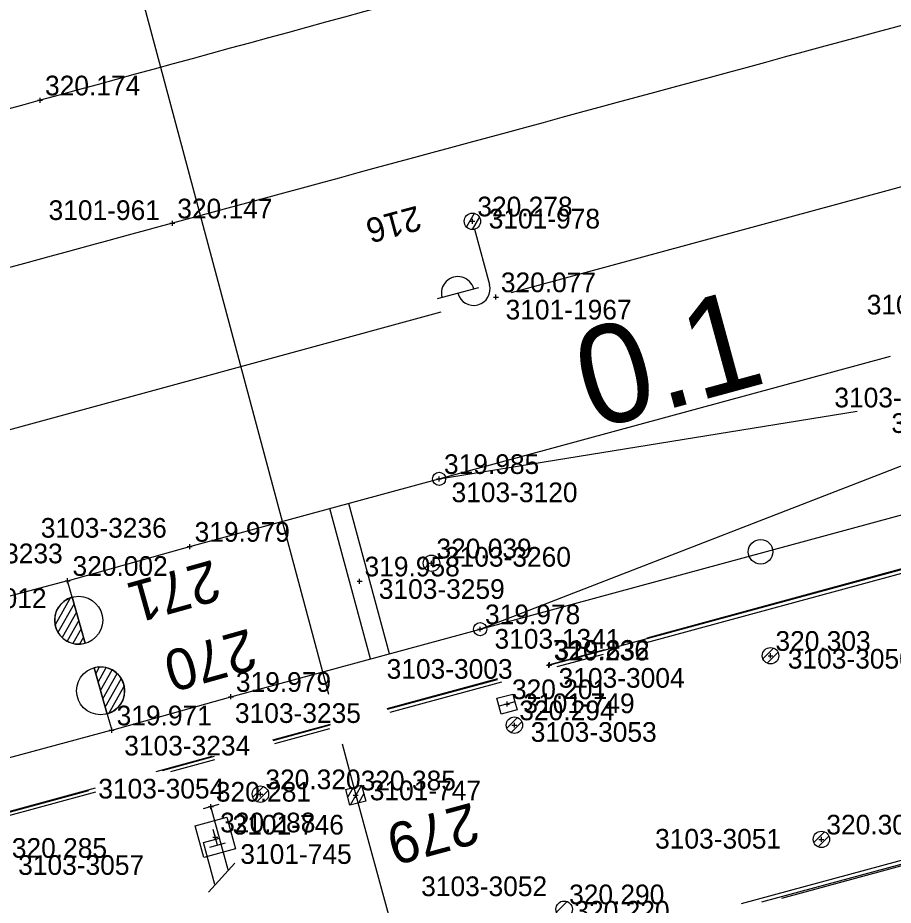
# Model space of a CAD drawing. Extents: x -821875 to -821475, y -1070280 to -1069975.
# Drawn here: x -821648.14 to -821621.48, y -1070208.12 to -1070181.08 of the extents above; entities that cross this region are included whole.
import ezdxf

# ---------------------------------------------------------------- set-up
doc = ezdxf.new("R2010")
doc.units = 0
for name, color, linetype in [('Vrstva 1', 7, 'Continuous'), ('Vrstva 10', 7, 'Continuous'), ('Vrstva 11', 7, 'Continuous'), ('Vrstva 14', 7, 'Continuous'), ('Vrstva 2', 7, 'Continuous'), ('Vrstva 25', 7, 'Continuous'), ('Vrstva 28', 7, 'Continuous'), ('Vrstva 3', 7, 'Continuous'), ('Vrstva 33', 7, 'Continuous'), ('Vrstva 36', 7, 'Continuous'), ('Vrstva 43', 7, 'Continuous'), ('Vrstva 60', 7, 'Continuous'), ('Vrstva 61', 7, 'Continuous'), ('Vrstva 7', 7, 'Continuous')]:
    doc.layers.add(name, color=color, linetype=linetype)

# ---------------------------------------------------------------- blocks, each defined once
blk = doc.blocks.new('BOD')
at = {"layer": 'Vrstva 3'}
for p, q in [((-0.15, 0), (0.15, 0)), ((0, -0.15), (0, 0.15))]:
    blk.add_line(p, q, dxfattribs=at)

msp = doc.modelspace()

# ---------------------------------------------------------------- linework, layer by layer
at = {"layer": 'Vrstva 1'}
for p, q in [((-821609.224, -1070182.961), (-821633.113, -1070189.465)), ((-821635.257, -1070190.05), (-821659.741, -1070196.727))]:
    msp.add_line(p, q, dxfattribs=at)
for points in [[(-821646.625, -1070198.235), (-821650.317, -1070199.215), (-821662.183, -1070202.42), (-821668.007, -1070204.011)], [(-821645.282, -1070202.79), (-821656.417, -1070205.79), (-821661.645, -1070207.21)]]:
    msp.add_lwpolyline(points, dxfattribs=at)
for points in [[(-821500, -1070134.157), (-821525.227, -1070140.424), (-821545.665, -1070145.962), (-821584.89, -1070156.649), (-821608.863, -1070163.173), (-821645.742, -1070173.228), (-821684.141, -1070183.689)], [(-821500, -1070139.002), (-821505.719, -1070140.359), (-821526.796, -1070145.75), (-821547.362, -1070151.333), (-821583.687, -1070161.245), (-821611.332, -1070168.765), (-821648.899, -1070179.006), (-821680.4, -1070187.609), (-821711.133, -1070195.974)], [(-821500, -1070143.947), (-821500.602, -1070144.082), (-821526.98, -1070150.62), (-821544.477, -1070155.432), (-821558.026, -1070159.151), (-821579.135, -1070164.951), (-821610.376, -1070173.463), (-821647.463, -1070183.595), (-821678.921, -1070192.191), (-821710.276, -1070200.761)], [(-821500, -1070148.817), (-821511.77, -1070151.622), (-821530.609, -1070156.564), (-821556.604, -1070163.701), (-821576.895, -1070169.217), (-821607.294, -1070177.525), (-821643.435, -1070187.343), (-821669.656, -1070194.488)]]:
    msp.add_spline(points, degree=3, dxfattribs=at)
at = {"layer": 'Vrstva 10'}
for p, q in [((-821642.019, -1070205.049), (-821642.501, -1070205.179)), ((-821641.738, -1070207.044), (-821642.26, -1070205.114)), ((-821641.536, -1070206.834), (-821642.332, -1070207.723))]:
    msp.add_line(p, q, dxfattribs=at)
msp.add_lwpolyline([(-821642.136, -1070207.489), (-821642.482, -1070206.21), (-821641.999, -1070206.079)], dxfattribs=at)
at = {"layer": 'Vrstva 11'}
for p, q in [((-821648.122, -1070166.406), (-821638.674, -1070201.687)), ((-821638.267, -1070203.204), (-821637.848, -1070204.77)), ((-821637.926, -1070204.532), (-821638.093, -1070204.822)), ((-821637.672, -1070204.465), (-821638.022, -1070205.076)), ((-821637.848, -1070204.77), (-821635.133, -1070214.658)), ((-821637.603, -1070204.721), (-821637.767, -1070205.007))]:
    msp.add_line(p, q, dxfattribs=at)
msp.add_lwpolyline([(-821637.542, -1070204.946), (-821638.024, -1070205.076), (-821638.154, -1070204.594), (-821637.672, -1070204.464)], close=True, dxfattribs=at)
msp.add_lwpolyline([(-821637.542, -1070204.946), (-821638.024, -1070205.076), (-821638.154, -1070204.594), (-821637.672, -1070204.464), (-821637.542, -1070204.946)], dxfattribs=at)
at = {"layer": 'Vrstva 14'}
for p, q in [((-821626.102, -1070208.071), (-821552.45, -1070188.031)), ((-821631.968, -1070200.811), (-821606.881, -1070193.985)), ((-821606.775, -1070194.079), (-821629.002, -1070200.121)), ((-821606.885, -1070193.956), (-821628.981, -1070199.983)), ((-821630.276, -1070200.336), (-821631.947, -1070200.792)), ((-821630.311, -1070200.477), (-821631.719, -1070200.86)), ((-821633.41, -1070201.319), (-821636.811, -1070202.244)), ((-821638.645, -1070202.742), (-821640.324, -1070203.198)), ((-821642.147, -1070203.694), (-821643.495, -1070204.06)), ((-821645.775, -1070204.68), (-821650.462, -1070205.954))]:
    msp.add_line(p, q, dxfattribs=at)
for points in [[(-821625.477, -1070208.02), (-821593.697, -1070199.421)], [(-821593.592, -1070199.416), (-821624.886, -1070207.92)], [(-821633.534, -1070201.224), (-821636.904, -1070202.14)], [(-821636.877, -1070202.147), (-821633.536, -1070201.238)], [(-821638.632, -1070202.61), (-821640.385, -1070203.087)], [(-821640.366, -1070203.097), (-821638.632, -1070202.625)], [(-821642.234, -1070203.589), (-821643.938, -1070204.053)], [(-821643.731, -1070204.012), (-821642.15, -1070203.582)], [(-821650.876, -1070205.957), (-821645.983, -1070204.625)], [(-821645.788, -1070204.556), (-821650.748, -1070205.905)]]:
    msp.add_lwpolyline(points, dxfattribs=at)
at = {"layer": 'Vrstva 2'}
for p, q in [((-821646.485, -1070198.73), (-821646.625, -1070198.235)), ((-821646.538, -1070198.749), (-821647.005, -1070199.576)), ((-821646.428, -1070198.935), (-821646.918, -1070199.806)), ((-821646.485, -1070198.73), (-821646.091, -1070200.14)), ((-821646.485, -1070198.73), (-821646.485, -1070198.73)), ((-821646.091, -1070200.14), (-821646.485, -1070198.73)), ((-821646.356, -1070199.19), (-821646.792, -1070199.964)), ((-821646.285, -1070199.446), (-821646.64, -1070200.075)), ((-821646.214, -1070199.701), (-821646.463, -1070200.144)), ((-821646.142, -1070199.957), (-821646.259, -1070200.165)), ((-821645.423, -1070202.295), (-821645.818, -1070200.886)), ((-821645.818, -1070200.886), (-821645.422, -1070202.295)), ((-821645.767, -1070201.069), (-821645.65, -1070200.861)), ((-821645.695, -1070201.324), (-821645.447, -1070200.882)), ((-821645.623, -1070201.579), (-821645.27, -1070200.95)), ((-821645.552, -1070201.835), (-821645.117, -1070201.061)), ((-821645.48, -1070202.09), (-821644.991, -1070201.219)), ((-821645.37, -1070202.276), (-821644.904, -1070201.448)), ((-821645.423, -1070202.295), (-821645.282, -1070202.79)), ((-821645.422, -1070202.295), (-821645.423, -1070202.295))]:
    msp.add_line(p, q, dxfattribs=at)
for points in [[(-821646.625, -1070198.235), (-821642.906, -1070197.195), (-821621.565, -1070191.392)], [(-821635.311, -1070195.13), (-821622.575, -1070193.064)], [(-821634.061, -1070199.709), (-821619.083, -1070193.903)], [(-821645.282, -1070202.79), (-821641.649, -1070201.769), (-821618.187, -1070195.399)]]:
    msp.add_lwpolyline(points, dxfattribs=at)
for centre, radius in [((-821635.311, -1070195.13), 0.2), ((-821646.288, -1070199.439), 0.731), ((-821634.061, -1070199.709), 0.2), ((-821645.621, -1070201.587), 0.731)]:
    msp.add_circle(centre, radius, dxfattribs=at)
for centre, start, end in [((-821646.288, -1070199.435), 105.643, 285.6038), ((-821645.62, -1070201.591), 285.7168, 105.6776)]:
    msp.add_arc(centre, 0.732, start, end, dxfattribs=at)
at = {"layer": 'Vrstva 25'}
for p, q in [((-821634.237, -1070187.04), (-821634.475, -1070187.455)), ((-821634.084, -1070187.149), (-821634.302, -1070187.53)), ((-821634.23, -1070187.523), (-821633.774, -1070189.212)), ((-821634.111, -1070189.304), (-821635.366, -1070189.643))]:
    msp.add_line(p, q, dxfattribs=at)
msp.add_circle((-821634.295, -1070187.282), 0.25, dxfattribs=at)
msp.add_circle((-821634.295, -1070187.282), 0.25, dxfattribs=at)
for centre, start, end in [((-821634.74, -1070189.468), 14.4192, 195.8243), ((-821634.256, -1070189.343), 195.1217, 15.1217)]:
    msp.add_arc(centre, 0.5, start, end, dxfattribs=at)
at = {"layer": 'Vrstva 28'}
msp.add_line((-821635.566, -1070197.702), (-821635.516, -1070197.702), dxfattribs=at)
msp.add_circle((-821635.541, -1070197.702), 0.25, dxfattribs=at)
at = {"layer": 'Vrstva 33'}
for p, q in [((-821642.063, -1070206.292), (-821642.193, -1070205.81)), ((-821641.822, -1070206.227), (-821642.304, -1070206.357))]:
    msp.add_line(p, q, dxfattribs=at)
msp.add_lwpolyline([(-821641.515, -1070206.403), (-821642.48, -1070206.664), (-821642.741, -1070205.699), (-821641.776, -1070205.438), (-821641.515, -1070206.403)], dxfattribs=at)
at = {"layer": 'Vrstva 36'}
for p, q in [((-821625.446, -1070200.611), (-821625.122, -1070200.288)), ((-821625.316, -1070200.746), (-821624.988, -1070200.418)), ((-821633.246, -1070202.726), (-821632.924, -1070202.403)), ((-821633.116, -1070202.861), (-821632.789, -1070202.534)), ((-821640.982, -1070204.828), (-821640.658, -1070204.505)), ((-821640.852, -1070204.963), (-821640.524, -1070204.636)), ((-821623.896, -1070206.207), (-821623.572, -1070205.884)), ((-821623.766, -1070206.342), (-821623.438, -1070206.014)), ((-821631.73, -1070208.334), (-821631.408, -1070208.011))]:
    msp.add_line(p, q, dxfattribs=at)
for centre in [(-821625.215, -1070200.519), (-821633.016, -1070202.634), (-821640.751, -1070204.736), (-821623.665, -1070206.115), (-821631.5, -1070208.242)]:
    msp.add_circle(centre, 0.25, dxfattribs=at)
at = {"layer": 'Vrstva 43'}
msp.add_lwpolyline([(-821633, -1070201.926), (-821632.935, -1070202.167), (-821633.417, -1070202.297), (-821633.547, -1070201.815), (-821633.065, -1070201.685), (-821633, -1070201.926), (-821633.482, -1070202.056)], dxfattribs=at)
at = {"layer": 'Vrstva 7'}
for p, q in [((-821636.82, -1070200.458), (-821638.064, -1070195.878)), ((-821637.399, -1070200.615), (-821638.643, -1070196.036))]:
    msp.add_line(p, q, dxfattribs=at)
msp.add_circle((-821625.518, -1070197.351), 0.375, dxfattribs=at)

# ---------------------------------------------------------------- block references
at = {"layer": 'Vrstva 60', "xscale": 0.5, "yscale": 0.5}
for p in [(-821647.463, -1070183.595), (-821643.435, -1070187.343), (-821634.295, -1070187.282), (-821633.579, -1070189.592), (-821635.311, -1070195.13), (-821642.906, -1070197.195), (-821635.541, -1070197.702), (-821646.625, -1070198.235), (-821637.731, -1070198.251), (-821634.061, -1070199.709), (-821625.215, -1070200.519), (-821631.968, -1070200.811), (-821631.947, -1070200.792), (-821641.649, -1070201.769), (-821633.241, -1070201.991), (-821645.282, -1070202.79), (-821633.016, -1070202.634), (-821640.751, -1070204.736), (-821637.848, -1070204.77), (-821642.26, -1070205.114), (-821642.128, -1070206.051), (-821623.665, -1070206.115)]:
    msp.add_blockref('BOD', p, dxfattribs=at)

# ---------------------------------------------------------------- texts
at = {"layer": 'Vrstva 11'}
msp.add_text('279', height=1.25, rotation=195.1227, dxfattribs=at).set_placement((-821634.304, -1070204.983))
at = {"layer": 'Vrstva 2'}
for s, rotation, p in [('271', 195.6234, (-821642.198, -1070197.586)), ('270', 195.6972, (-821641.098, -1070199.682))]:
    msp.add_text(s, height=1.25, rotation=rotation, dxfattribs=at).set_placement(p)
at = {"layer": 'Vrstva 25'}
msp.add_text('216', height=0.75, rotation=195.1216, dxfattribs=at).set_placement((-821635.981, -1070186.801))
at = {"layer": 'Vrstva 60'}
for s, p in [('3101-961', (-821647.204, -1070187.242)), ('3101-978', (-821633.798, -1070187.501)), ('3101-1967', (-821633.284, -1070190.273)), ('3103-3237', (-821622.285, -1070190.12)), ('3103-3238', (-821623.271, -1070192.952)), ('3103-3239', (-821621.533, -1070193.73)), ('3103-3120', (-821634.93, -1070195.84)), ('3103-3236', (-821647.442, -1070196.922)), ('3103-3233', (-821650.611, -1070197.702)), ('3103-3260', (-821635.131, -1070197.805)), ('3103-3259', (-821637.147, -1070198.787)), ('3103-1341', (-821633.622, -1070200.304)), ('3103-3050', (-821624.689, -1070200.911)), ('3103-3003', (-821636.907, -1070201.221)), ('3103-3004', (-821631.669, -1070201.494)), ('3101-749', (-821632.744, -1070202.268)), ('3103-3235', (-821641.528, -1070202.566)), ('3103-3053', (-821632.519, -1070203.142)), ('3103-3234', (-821644.9, -1070203.558)), ('3103-3054', (-821645.691, -1070204.869)), ('3101-747', (-821637.422, -1070204.923)), ('3101-746', (-821641.601, -1070205.967)), ('3103-3051', (-821628.731, -1070206.396)), ('3101-745', (-821641.363, -1070206.861)), ('3103-3057', (-821648.131, -1070207.196)), ('3103-3052', (-821635.856, -1070207.843))]:
    msp.add_text(s, height=0.6, dxfattribs=at).set_placement(p)
at = {"layer": 'Vrstva 61'}
for s, p in [('320.174', (-821647.313, -1070183.445)), ('320.147', (-821643.285, -1070187.193)), ('320.278', (-821634.145, -1070187.132)), ('320.077', (-821633.429, -1070189.442)), ('319.985', (-821635.161, -1070194.98)), ('319.979', (-821642.756, -1070197.045)), ('320.039', (-821635.391, -1070197.552)), ('320.002', (-821646.475, -1070198.085)), ('319.958', (-821637.581, -1070198.101)), ('320.012', (-821650.167, -1070199.065)), ('319.978', (-821633.911, -1070199.559)), ('320.303', (-821625.065, -1070200.369)), ('320.236', (-821631.818, -1070200.661)), ('319.832', (-821631.797, -1070200.642)), ('319.979', (-821641.499, -1070201.619)), ('320.201', (-821633.091, -1070201.841)), ('320.294', (-821632.866, -1070202.484)), ('319.971', (-821645.132, -1070202.64)), ('320.320', (-821640.601, -1070204.586)), ('320.385', (-821637.698, -1070204.62)), ('320.281', (-821642.11, -1070204.964)), ('320.288', (-821641.978, -1070205.901)), ('320.303', (-821623.515, -1070205.965)), ('320.285', (-821648.324, -1070206.676)), ('320.290', (-821631.35, -1070208.092)), ('320.220', (-821631.189, -1070208.589))]:
    msp.add_text(s, height=0.6, dxfattribs=at).set_placement(p)
at = {"layer": 'Vrstva 7'}
msp.add_text('0.1', height=3, rotation=15.228, dxfattribs=at).set_placement((-821630.647, -1070193.644))

doc.saveas('drawing.dxf')
